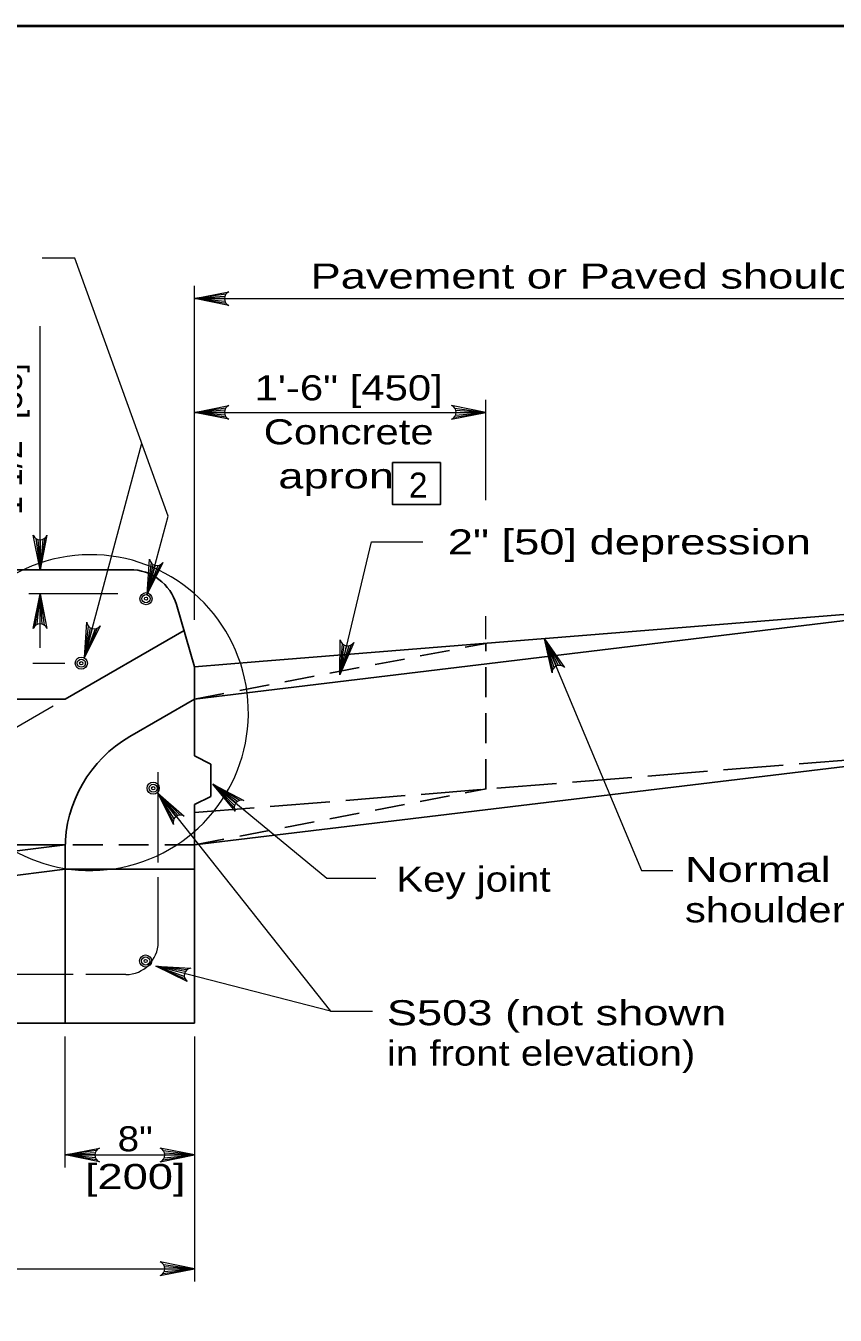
# Model space of a CAD drawing. Extents: x 758.3 to 792.3, y 849.7 to 893.7.
# Drawn here: x 780.94 to 785.98, y 863.16 to 871.19 of the extents above; entities that cross this region are included whole.
import ezdxf
from ezdxf.enums import TextEntityAlignment as Align

# ---------------------------------------------------------------- set-up
doc = ezdxf.new("R2010")
doc.units = 0
doc.header["$LTSCALE"] = 0.062
doc.linetypes.add('LONG_DASHED', pattern=[7.5, 6, -1.5])
doc.linetypes.add('MEDIUM_DASHED', pattern=[4.5, 3, -1.5])
doc.layers.add('1', color=7, linetype='Continuous', lineweight=13)

msp = doc.modelspace()

# ---------------------------------------------------------------- linework, layer by layer
at = {"layer": '1', "lineweight": 25}
for p, q in [((760.3205, 871.18817), (791.8205, 871.18817)), ((781.58392, 867.80392), (778.25792, 867.80392)), ((781.987, 867.19892), (781.87417, 867.58625)), ((781.987, 866.99775), (786.9905, 867.60233)), ((782.38925, 867.23167), (786.9905, 867.60233)), ((781.92108, 867.42525), (781.18075, 866.99767)), ((781.98692, 867.19925), (782.38925, 867.23167)), ((781.987, 866.645), (781.987, 867.19892)), ((781.18075, 866.99767), (778.76192, 866.99767)), ((781.987, 866.99775), (781.58375, 866.765)), ((781.987, 866.09075), (786.9905, 866.69533)), ((781.987, 866.645), (782.08783, 866.59458)), ((782.08783, 866.393), (782.08783, 866.59458)), ((781.987, 866.34267), (782.08783, 866.393)), ((781.987, 864.98217), (781.987, 866.34267)), ((781.18075, 864.98217), (781.18075, 866.06683)), ((781.18075, 865.93958), (780.47375, 865.85117)), ((781.18075, 865.93958), (781.98717, 865.93958)), ((777.95558, 864.98217), (781.987, 864.98217))]:
    msp.add_line(p, q, dxfattribs=at)
at = {"layer": '1'}
for p, q in [((781.24175, 869.74292), (781.03883, 869.74292)), ((781.82275, 868.13708), (781.24175, 869.74292)), ((781.987, 867.49142), (781.987, 869.56917)), ((782.18092, 869.51758), (781.987, 869.4905)), ((782.17433, 869.50417), (781.987, 869.4905)), ((782.17233, 869.4905), (781.987, 869.4905)), ((782.17575, 869.47308), (781.987, 869.4905)), ((782.18325, 869.4605), (781.987, 869.4905)), ((781.987, 869.4905), (786.9905, 869.4905)), ((781.02517, 867.80392), (781.02517, 869.31858)), ((783.80117, 868.2365), (783.80117, 868.86117)), ((782.18092, 868.80958), (781.987, 868.7825)), ((782.17433, 868.79617), (781.987, 868.7825)), ((782.17233, 868.7825), (781.987, 868.7825)), ((782.17575, 868.76508), (781.987, 868.7825)), ((782.18325, 868.7525), (781.987, 868.7825)), ((781.987, 868.7825), (783.80117, 868.7825)), ((783.605, 868.7525), (783.80117, 868.7825)), ((783.60725, 868.80958), (783.80117, 868.7825)), ((783.61242, 868.76508), (783.80117, 868.7825)), ((783.61383, 868.79617), (783.80117, 868.7825)), ((783.61583, 868.7825), (783.80117, 868.7825)), ((781.30217, 867.25825), (781.65908, 868.59042)), ((781.69275, 867.65208), (781.82275, 868.13708)), ((780.998, 867.99775), (781.02517, 867.80392)), ((781.01142, 867.99125), (781.02517, 867.80392)), ((781.05508, 868.00008), (781.02517, 867.80392)), ((781.04258, 867.99267), (781.02517, 867.80392)), ((781.02517, 867.98925), (781.02517, 867.80392)), ((781.71675, 867.84642), (781.69275, 867.65208)), ((781.728, 867.83658), (781.69275, 867.65208)), ((781.7725, 867.83383), (781.69275, 867.65208)), ((781.74075, 867.83108), (781.69275, 867.65208)), ((781.75842, 867.82992), (781.69275, 867.65208)), ((781.50833, 867.65275), (780.95567, 867.65275)), ((780.99517, 867.45658), (781.02517, 867.65275)), ((781.00775, 867.464), (781.02517, 867.65275)), ((781.02517, 867.31667), (781.02517, 867.65275)), ((781.02517, 867.46742), (781.02517, 867.65275)), ((781.03883, 867.46542), (781.02517, 867.65275)), ((781.05225, 867.45883), (781.02517, 867.65275)), ((783.80117, 867.37133), (783.80117, 867.51367)), ((781.32542, 867.45267), (781.30217, 867.25825)), ((781.33675, 867.44292), (781.30217, 867.25825)), ((781.38125, 867.44033), (781.30217, 867.25825)), ((781.3495, 867.4375), (781.30217, 867.25825)), ((781.36717, 867.43633), (781.30217, 867.25825)), ((782.90508, 867.34492), (782.89217, 867.1495)), ((782.91692, 867.33575), (782.89217, 867.1495)), ((782.9615, 867.3355), (782.89217, 867.1495)), ((782.92992, 867.331), (782.89217, 867.1495)), ((782.94767, 867.33083), (782.89217, 867.1495)), ((784.24017, 867.20467), (784.16508, 867.37417)), ((784.22558, 867.1945), (784.16508, 867.37417)), ((784.21708, 867.18258), (784.16508, 867.37417)), ((784.2535, 867.20842), (784.16508, 867.37417)), ((784.26842, 867.20783), (784.16508, 867.37417)), ((780.98042, 867.22175), (781.1795, 867.22175)), ((781.1055, 866.95425), (780.3815, 866.53625)), ((781.76025, 865.98208), (781.76025, 866.54417)), ((782.24458, 866.35208), (782.1005, 866.46875)), ((782.23625, 866.33642), (782.1005, 866.46875)), ((782.23408, 866.322), (782.1005, 866.46875)), ((782.25475, 866.3615), (782.1005, 866.46875)), ((782.26825, 866.36775), (782.1005, 866.46875)), ((781.8715, 866.26667), (781.75767, 866.41292)), ((781.85983, 866.25325), (781.75767, 866.41292)), ((781.8545, 866.23967), (781.75767, 866.41292)), ((781.88358, 866.2735), (781.75767, 866.41292)), ((781.89817, 866.2765), (781.75767, 866.41292)), ((781.76025, 865.48608), (781.76025, 865.89058)), ((781.92408, 865.2905), (781.74475, 865.337)), ((781.92308, 865.27275), (781.74475, 865.337)), ((781.92708, 865.25875), (781.74475, 865.337)), ((781.9295, 865.30325), (781.74475, 865.337)), ((781.93925, 865.31458), (781.74475, 865.337)), ((781.23192, 865.2845), (780.83842, 865.2845)), ((781.55867, 865.2845), (781.30967, 865.2845)), ((782.83342, 865.05742), (783.09492, 865.05742)), ((781.18075, 864.08308), (781.18075, 864.89833)), ((781.987, 864.89833), (781.987, 863.37508)), ((781.37467, 864.18892), (781.18075, 864.16175)), ((781.36808, 864.1755), (781.18075, 864.16175)), ((781.18075, 864.16175), (781.76542, 864.16175)), ((781.36608, 864.16175), (781.18075, 864.16175)), ((781.3695, 864.14433), (781.18075, 864.16175)), ((781.37692, 864.13175), (781.18075, 864.16175)), ((781.76542, 864.16175), (781.98725, 864.16175)), ((781.79108, 864.13175), (781.98725, 864.16175)), ((781.79333, 864.18892), (781.98725, 864.16175)), ((781.7985, 864.14433), (781.98725, 864.16175)), ((781.79992, 864.1755), (781.98725, 864.16175)), ((781.80192, 864.16175), (781.98725, 864.16175)), ((781.79317, 863.48092), (781.987, 863.45375)), ((777.95558, 863.45375), (781.987, 863.45375)), ((781.79083, 863.42375), (781.987, 863.45375)), ((781.79825, 863.43633), (781.987, 863.45375)), ((781.79975, 863.4675), (781.987, 863.45375)), ((781.80167, 863.45375), (781.987, 863.45375))]:
    msp.add_line(p, q, dxfattribs=at)
at = {"layer": '1', "linetype": 'MEDIUM_DASHED', "lineweight": 25}
for p, q in [((781.98692, 866.99767), (783.80117, 867.34542)), ((783.80117, 866.43833), (783.80117, 867.34542)), ((781.987, 866.09075), (783.80167, 866.44075)), ((781.987, 866.09075), (781.18075, 866.09075))]:
    msp.add_line(p, q, dxfattribs=at)
at = {"layer": '1', "linetype": 'LONG_DASHED', "lineweight": 25}
msp.add_line((781.987, 866.29225), (786.9905, 866.69533), dxfattribs=at)
at = {"layer": '1', "lineweight": 40}
msp.add_lwpolyline([(760.3205, 871.18817), (791.8205, 871.18817), (791.8205, 850.18817), (760.3205, 850.18817)], close=True, dxfattribs=at)
at = {"layer": '1'}
for points in [[(782.20117, 869.44767), (781.987, 869.4905), (782.20117, 869.53333)], [(782.20117, 868.73967), (781.987, 868.7825), (782.20117, 868.82533)], [(783.587, 868.73967), (783.80117, 868.7825), (783.587, 868.82533)], [(781.068, 868.01808), (781.02517, 867.80392), (780.98233, 868.01808)], [(782.89217, 867.1495), (783.0875, 867.977), (783.40892, 867.977)], [(781.78958, 867.84792), (781.69275, 867.65208), (781.70683, 867.87008)], [(780.98233, 867.43858), (781.02517, 867.65275), (781.068, 867.43858)], [(781.39825, 867.45442), (781.30217, 867.25825), (781.31542, 867.47633)], [(782.97767, 867.3505), (782.89217, 867.1495), (782.89383, 867.36792)], [(784.21267, 867.161), (784.16508, 867.37417), (784.291, 867.19567)], [(784.16508, 867.37417), (784.77, 865.932), (784.96533, 865.932)], [(782.24, 866.30067), (782.1005, 866.46875), (782.29392, 866.36725)], [(782.1005, 866.46875), (782.80992, 865.88333), (783.1145, 865.88333)], [(781.75767, 866.41292), (782.83342, 865.05742), (781.74475, 865.337)], [(781.85542, 866.21758), (781.75767, 866.41292), (781.923, 866.27017)], [(781.94133, 865.24183), (781.74475, 865.337), (781.96275, 865.32475)], [(781.39492, 864.11892), (781.18075, 864.16175), (781.39492, 864.20458)], [(781.77308, 864.11892), (781.98725, 864.16175), (781.77308, 864.20458)], [(781.77283, 863.41092), (781.987, 863.45375), (781.77283, 863.49658)]]:
    msp.add_lwpolyline(points, dxfattribs=at)
at = {"layer": '1', "lineweight": 25}
for points in [[(783.21933, 868.47017), (783.21933, 868.20842), (783.51792, 868.20842), (783.51792, 868.47017)], [(781.18075, 866.09075), (778.76192, 866.09075), (779.97133, 865.93958)]]:
    msp.add_lwpolyline(points, close=True, dxfattribs=at)
at = {"layer": '1'}
for centre, start, end in [((782.2185, 869.49051), 112.08782, 247.91395), ((782.2185, 868.78251), 112.08782, 247.91395), ((783.56972, 868.78251), 292.08605, 67.91218), ((781.02509, 868.03535), 202.08782, 337.91395), ((781.75264, 867.8757), 187.07922, 322.90535), ((781.02518, 867.42126), 22.08782, 157.91395), ((781.3612, 867.48211), 187.30821, 323.13434), ((782.93924, 867.37617), 190.34727, 326.17339), ((784.25887, 867.16253), 45.98826, 181.81439), ((782.28045, 866.3231), 73.0926, 208.91873), ((781.89988, 866.23025), 59.98014, 195.80626), ((781.9688, 865.27896), 97.5554, 233.38153), ((781.41222, 864.16181), 112.08782, 247.91395), ((781.75577, 864.16181), 292.08605, 67.91218), ((781.75557, 863.45382), 292.08605, 67.91218)]:
    msp.add_arc(centre, 0.04623, start, end, dxfattribs=at)
for centre, major_axis, start_param, end_param in [((781.33918, 866.91454), (0.98266, 0), 3.5976271, 9.4070997), ((781.5587, 865.48606), (0.20157, 0), 4.712389, 6.2831853)]:
    msp.add_ellipse(centre, major_axis=major_axis, ratio=0.999895, start_param=start_param, end_param=end_param, dxfattribs=at)
at = {"layer": '1', "lineweight": 25}
for centre, major_axis, start_param, end_param in [((781.58386, 867.50156), (0.30236, 0), 0.283624, 1.5707963), ((781.98704, 866.0668), (-0.80629, 0), 5.2361, 6.2831853)]:
    msp.add_ellipse(centre, major_axis=major_axis, ratio=0.999895, start_param=start_param, end_param=end_param, dxfattribs=at)
at = {"layer": '1'}
for centre, major_axis in [((781.68468, 867.6232), (0.03779, 0)), ((781.68468, 867.6232), (0.0252, 0)), ((781.68468, 867.6232), (0.01008, 0)), ((781.28153, 867.22171), (0.03779, 0)), ((781.28153, 867.22171), (0.0252, 0)), ((781.28153, 867.22171), (0.01008, 0)), ((781.72953, 866.44402), (0.03779, 0)), ((781.72953, 866.44402), (0.0252, 0)), ((781.72953, 866.44402), (0.01008, 0)), ((781.68216, 865.36895), (0.03779, 0)), ((781.68216, 865.36895), (0.0252, 0)), ((781.68216, 865.36895), (0.01008, 0))]:
    msp.add_ellipse(centre, major_axis=major_axis, ratio=0.999895, dxfattribs=at)

# ---------------------------------------------------------------- texts
for s, width, p in [('Pavement or Paved shoulder', 1.35, (784.525, 869.553)), ('1\'-6" [450]', 1.25, (782.94654, 868.8575)), ('Concrete', 1.25, (782.9465, 868.5835)), ('apron  ', 1.35, (782.94662, 868.3095)), ('8"', 1.15, (781.61746, 864.18467)), ('[200]', 1.35, (781.61754, 863.95))]:
    msp.add_text(s, height=0.156, dxfattribs=dict(at, width=width)).set_placement(p, align=Align.CENTER)
msp.add_text('1 1/2" [38]', height=0.156, rotation=90, dxfattribs=at).set_placement((780.91225, 868.14525))
msp.add_text('2', height=0.156, dxfattribs=at).set_placement((783.32125, 868.252))
for s, width, p in [('2" [50] depression', 1.35, (783.56367, 867.89858)), ('Key joint', 1.2, (783.24283, 865.80008)), ('Normal pavemnt or', 1.35, (785.03992, 865.86067)), ('shoulder slope', 1.25, (785.03992, 865.6095)), ('S503 (not shown', 1.35, (783.18383, 864.96908)), ('in front elevation)', 1.2, (783.18383, 864.71792))]:
    msp.add_text(s, height=0.156, dxfattribs=dict(at, width=width)).set_placement(p)

doc.saveas('drawing.dxf')
